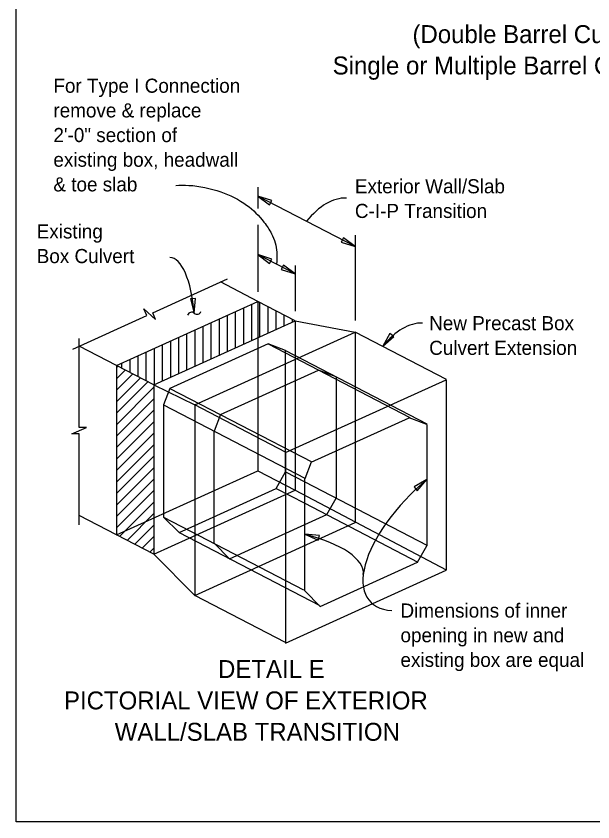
# Model space of a CAD drawing. Extents: x 0 to 123, y 0 to 78.
# Drawn here: x 0 to 24.7, y 0 to 34.5 of the extents above; entities that cross this region are included whole.
import ezdxf

# ---------------------------------------------------------------- set-up
doc = ezdxf.new("R2010")
doc.units = 0
for name, color, linetype in [('Dimension', 7, 'Continuous'), ('ExistSuperStruct', 7, 'Continuous'), ('Miscellaneous', 7, 'Continuous'), ('Miscellaneous1', 7, 'Continuous'), ('Patterning', 7, 'Continuous'), ('SubStrConc', 7, 'Continuous'), ('SubStrConc_h', 7, 'Continuous'), ('Symbols', 7, 'Continuous')]:
    doc.layers.add(name, color=color, linetype=linetype)

msp = doc.modelspace()

# ---------------------------------------------------------------- linework, layer by layer
at = {"layer": 'Dimension'}
for p, q in [((10.351, 27.18), (10.351, 26.268)), ((14.526, 24.632), (10.351, 26.8)), ((10.351, 25.57), (10.351, 22.703)), ((14.526, 25.129), (14.526, 21.463)), ((11.951, 23.463), (10.351, 24.294)), ((11.951, 23.824), (11.951, 21.866))]:
    msp.add_line(p, q, dxfattribs=at)
for points in [[(7.628, 21.781), (7.682, 22.412), (7.471, 22.395)], [(15.704, 20.364), (16.176, 20.786), (16.011, 20.918)], [(17.587, 14.666), (17.042, 14.342), (17.179, 14.181)], [(12.362, 12.318), (12.942, 12.063), (12.993, 12.268)]]:
    msp.add_lwpolyline(points, close=True, dxfattribs=at)
for centre, major_axis, ratio, start_param, end_param in [((13.971, 18.064), (-0.174, -8.651), 0.411326, 3.141808, 3.634993), ((6.61, 21.119), (0.022, -3.046), 0.343762, 1.787422, 3.141593), ((17.236, 12.711), (-0.174, -8.651), 0.411326, 3.141808, 3.634993), ((18.931, 12.804), (3.787, 3.349), 0.45249, 1.52585, 3.559483), ((10.919, 11.061), (-3.949, 0.469), 0.376773, 3.141593, 4.383632)]:
    msp.add_ellipse(centre, major_axis=major_axis, ratio=ratio, start_param=start_param, end_param=end_param, dxfattribs=at)
msp.add_spline([(6.835, 27.256), (7.393, 27.256), (8.767, 26.978), (9.873, 26.412), (10.615, 25.677), (10.939, 25.181), (11.163, 24.399), (11.151, 23.879)], degree=3, dxfattribs=at)
at = {"layer": 'ExistSuperStruct'}
for p, q in [((10.351, 22.288), (8.751, 23.119)), ((4.299, 19.543), (2.699, 20.374)), ((4.299, 12.292), (2.699, 13.123))]:
    msp.add_line(p, q, dxfattribs=at)
at = {"layer": 'Miscellaneous'}
for p, q in [((10.095, 20.615), (10.095, 22.172)), ((10.443, 20.773), (10.443, 22.24)), ((9.4, 20.3), (9.4, 21.857)), ((9.748, 20.457), (9.748, 22.014)), ((10.79, 20.931), (10.79, 22.06)), ((11.138, 21.088), (11.138, 21.879)), ((8.705, 19.984), (8.705, 21.541)), ((9.052, 20.142), (9.052, 21.699)), ((11.486, 21.246), (11.486, 21.699)), ((11.833, 21.404), (11.833, 21.518)), ((7.662, 19.511), (7.662, 21.068)), ((8.01, 19.669), (8.01, 21.226)), ((8.357, 19.827), (8.357, 21.384)), ((6.967, 19.196), (6.967, 20.753)), ((7.314, 19.354), (7.314, 20.911)), ((6.272, 18.881), (6.272, 20.437)), ((6.619, 19.038), (6.619, 20.595)), ((5.576, 18.88), (5.576, 20.122)), ((5.924, 18.723), (5.924, 20.28)), ((4.881, 19.241), (4.881, 19.807)), ((5.229, 19.06), (5.229, 19.964)), ((4.299, 19.467), (4.349, 19.517)), ((4.299, 18.976), (4.673, 19.349)), ((4.534, 19.421), (4.534, 19.649)), ((4.299, 18.484), (4.996, 19.181)), ((4.299, 17.992), (5.32, 19.013)), ((4.299, 17.501), (5.643, 18.845)), ((4.299, 17.009), (5.899, 18.609)), ((4.299, 16.518), (5.899, 18.118)), ((4.299, 16.026), (5.899, 17.626)), ((4.299, 15.534), (5.899, 17.135)), ((4.299, 15.043), (5.899, 16.643)), ((4.299, 14.551), (5.899, 16.151)), ((4.299, 14.06), (5.899, 15.66)), ((4.299, 13.568), (5.899, 15.168)), ((4.299, 13.077), (5.899, 14.677)), ((4.299, 12.585), (5.899, 14.185)), ((4.43, 12.224), (5.899, 13.693)), ((4.754, 12.056), (5.899, 13.202)), ((5.077, 11.888), (5.899, 12.71)), ((5.401, 11.72), (5.899, 12.219)), ((5.724, 11.552), (5.899, 11.727))]:
    msp.add_line(p, q, dxfattribs=at)
at = {"layer": 'Miscellaneous1'}
msp.add_lwpolyline([(0, 77.856), (123.127, 77.856), (123.127, 0), (0, 0)], close=True, dxfattribs=at)
at = {"layer": 'Patterning'}
msp.add_lwpolyline([(0, 77.91), (123.2, 77.91), (123.2, 0), (0, 0)], close=True, dxfattribs=at)
at = {"layer": 'SubStrConc'}
for p, q in [((4.299, 19.543), (10.351, 22.288)), ((11.951, 21.457), (10.351, 22.288)), ((5.899, 18.712), (11.951, 21.457)), ((11.951, 21.457), (14.526, 20.975)), ((7.648, 17.855), (14.526, 20.975)), ((18.435, 18.945), (14.526, 20.975)), ((4.299, 19.543), (4.299, 12.292)), ((5.899, 18.712), (4.299, 19.543)), ((5.899, 18.712), (5.899, 11.461)), ((5.899, 18.712), (7.648, 17.855)), ((11.534, 15.814), (18.411, 18.934)), ((18.411, 18.934), (18.411, 10.776)), ((7.648, 17.855), (7.648, 9.697)), ((11.534, 15.838), (7.648, 17.855)), ((12.634, 15.401), (16.834, 17.306)), ((17.587, 17.015), (16.834, 17.306)), ((17.587, 17.015), (17.587, 11.823)), ((13.702, 15.885), (13.702, 13.864)), ((11.534, 15.814), (11.534, 7.656)), ((12.634, 15.401), (12.362, 14.696)), ((12.362, 9.891), (12.362, 14.696)), ((12.362, 14.56), (17.587, 11.846)), ((13.3, 13.157), (13.702, 13.864)), ((12.362, 13.644), (17.209, 11.127)), ((12.362, 12.732), (13.3, 13.157)), ((5.899, 11.461), (4.299, 12.292)), ((17.185, 11.116), (17.587, 11.823)), ((5.899, 11.461), (7.648, 9.697)), ((13.024, 9.229), (17.185, 11.116)), ((11.534, 7.656), (18.411, 10.776)), ((11.534, 7.679), (7.648, 9.697)), ((12.362, 9.891), (13.024, 9.229))]:
    msp.add_line(p, q, dxfattribs=at)
at = {"layer": 'SubStrConc_h'}
for p, q in [((10.351, 22.288), (10.351, 15.037)), ((11.951, 21.457), (11.951, 16.642)), ((14.526, 20.975), (14.526, 12.812)), ((10.787, 20.47), (16.858, 17.317)), ((11.54, 20.179), (17.587, 17.039)), ((8.749, 17.442), (12.949, 19.347)), ((13.702, 19.056), (12.949, 19.347)), ((13.702, 19.056), (13.702, 15.885)), ((6.586, 18.565), (12.658, 15.412)), ((6.314, 17.86), (12.362, 14.719)), ((8.749, 17.442), (8.477, 16.737)), ((8.477, 11.932), (8.477, 16.737)), ((11.951, 16.642), (11.951, 14.206)), ((4.299, 12.292), (10.351, 15.037)), ((10.351, 15.037), (11.951, 14.206)), ((11.54, 14.987), (12.362, 14.56)), ((5.899, 11.461), (11.951, 14.206)), ((11.138, 14.28), (12.362, 13.644)), ((11.951, 14.206), (18.411, 10.793)), ((6.314, 13.055), (12.313, 9.939)), ((7.648, 9.697), (14.521, 12.815)), ((9.139, 11.27), (12.362, 12.732)), ((6.977, 12.392), (12.975, 9.277)), ((8.477, 11.932), (9.139, 11.27))]:
    msp.add_line(p, q, dxfattribs=at)
for points in [[(11.54, 19.62), (11.54, 20.179), (10.787, 20.47), (6.586, 18.565), (6.314, 17.86), (6.314, 13.055), (6.977, 12.392), (7.648, 12.697)], [(7.648, 12.697), (11.138, 14.28), (11.54, 14.987), (11.54, 19.62)]]:
    msp.add_lwpolyline(points, dxfattribs=at)
at = {"layer": 'Symbols'}
for points in [[(10.351, 26.8), (10.857, 26.419), (10.954, 26.606)], [(14.526, 24.632), (14.021, 25.014), (13.923, 24.826)], [(10.351, 24.294), (10.857, 23.913), (10.954, 24.1)], [(11.951, 23.463), (11.445, 23.845), (11.348, 23.657)]]:
    msp.add_lwpolyline(points, close=True, dxfattribs=at)
for points in [[(2.423, 20.248), (5.602, 21.691), (5.474, 21.973), (5.976, 21.52), (5.848, 21.802), (9.059, 23.259)], [(2.699, 12.721), (2.699, 16.613), (2.389, 16.613), (3.009, 16.883), (2.699, 16.883), (2.699, 20.693)]]:
    msp.add_lwpolyline(points, dxfattribs=at)
for centre, start, end in [((7.511, 21.646), 48.9165, 160.6437), ((7.746, 21.916), 228.9165, 340.6437)]:
    msp.add_arc(centre, 0.179, start, end, dxfattribs=at)

# ---------------------------------------------------------------- texts
at = {"layer": 'Dimension'}
for s, height, p in [('(Double Barrel Culvert shown,', 0.768, (16.975, 33.35)), ('Single or Multiple Barrel Culvert similar)', 0.768, (13.556, 32.006)), ('For Type I Connection', 0.6048, (1.597, 31.222)), ('remove & replace', 0.6048, (1.597, 30.166)), ('2\'-0" section of', 0.6048, (1.597, 29.11)), ('existing box, headwall', 0.6048, (1.597, 28.054)), ('& toe slab', 0.6048, (1.597, 26.998)), ('Exterior Wall/Slab ', 0.6048, (14.508, 26.916)), ('C-I-P Transition ', 0.6048, (14.508, 25.86)), ('Existing', 0.6048, (0.882, 24.983)), ('Box Culvert', 0.6048, (0.882, 23.927)), ('New Precast Box', 0.6048, (17.69, 21.053)), ('Culvert Extension', 0.6048, (17.69, 19.997)), ('Dimensions of inner', 0.6048, (16.461, 8.748)), ('opening in new and', 0.6048, (16.461, 7.692)), ('existing box are equal', 0.6048, (16.461, 6.636)), ('DETAIL E', 0.768, (8.647, 6.161)), ('PICTORIAL VIEW OF EXTERIOR', 0.768, (2.05, 4.817)), ('WALL/SLAB TRANSITION', 0.768, (4.222, 3.473))]:
    msp.add_text(s, height=height, dxfattribs=at).set_placement(p)

doc.saveas('drawing.dxf')
